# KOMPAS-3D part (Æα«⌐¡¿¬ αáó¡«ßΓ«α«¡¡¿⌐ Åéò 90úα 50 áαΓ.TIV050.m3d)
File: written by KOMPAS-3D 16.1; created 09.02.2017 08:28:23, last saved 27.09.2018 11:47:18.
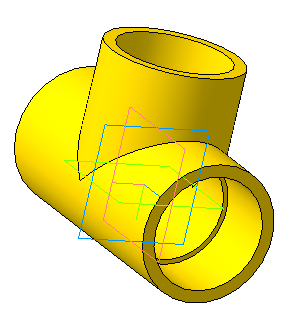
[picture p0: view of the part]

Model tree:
1. Эскиз:1
2. Операция выдавливания:9
     Расстояние 1 = 58
3. Массив по концентрической сетке:1  (with: Операция выдавливания:9, Эскиз:1)  (3 pattern instances)
     Геометрический массив = 2; Шаг 2 = 180
4. Эскиз:20
5. Вырезать элемент выдавливания:6
     Расстояние 1 = 116
6. Эскиз:21
7. Вырезать элемент выдавливания:7
     Расстояние 1 = 58
8. Эскиз:22
9. Вырезать элемент выдавливания:8
     Расстояние 1 = 31
10. Массив по концентрической сетке:3  (with: Вырезать элемент выдавливания:8, Эскиз:22)  (labels: Полипропилен  ГОСТ 26996-86)  (3 pattern instances)
     Геометрический массив = 2; Шаг 2 = 180

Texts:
  Тройник равносторонний ПВХ 90гр 50 арт.TIV050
